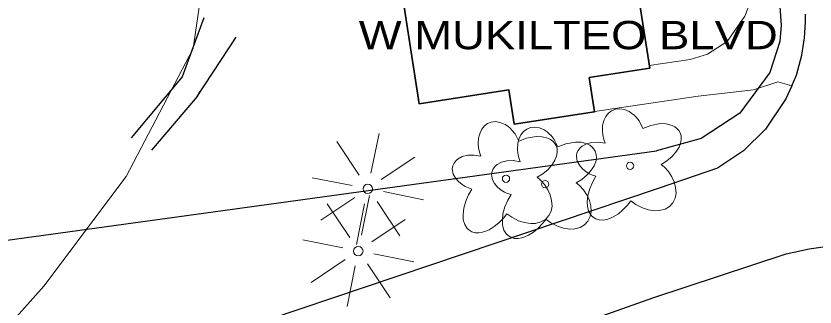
# Model space of a CAD drawing. Extents: x -861682 to -858969, y -1797841 to -1795153.
# Drawn here: x -859343 to -859173.6, y -1796365.6 to -1796304 of the extents above; entities that cross this region are included whole.
import ezdxf

# ---------------------------------------------------------------- set-up
doc = ezdxf.new("R2010")
doc.units = 0
doc.header["$LTSCALE"] = 2.4
for name, color, linetype, lineweight in [('10', 7, 'Continuous', 25), ('11', 7, 'Continuous', 13), ('12', 7, 'Continuous', 35), ('14', 7, 'Continuous', 25), ('17', 7, 'Continuous', 13), ('18', 7, 'Continuous', 13), ('42', 7, 'Continuous', 25), ('46', 7, 'Continuous', 13)]:
    doc.layers.add(name, color=color, linetype=linetype, lineweight=lineweight)

msp = doc.modelspace()

# ---------------------------------------------------------------- linework, layer by layer
at = {"layer": '10'}
for points in [[(-859178.581, -1796318.805), (-859177.592, -1796316.526), (-859176.417, -1796312.281), (-859175.841, -1796308.614), (-859175.653, -1796305.314), (-859175.676, -1796303.62)], [(-859178.581, -1796318.805), (-859179.784, -1796321.576), (-859184.102, -1796327.95), (-859188.824, -1796332.564), (-859194.317, -1796336.227)], [(-859194.317, -1796336.227), (-859199.045, -1796337.856), (-859206.902, -1796340.557), (-859310.306, -1796375.338)], [(-859179.756, -1796354.374), (-859174.867, -1796353.331), (-859165.467, -1796352.018), (-859159.969, -1796351.66), (-859156.664, -1796351.588), (-859155.562, -1796351.589), (-859151.156, -1796351.708), (-859147.857, -1796351.924), (-859141.289, -1796352.676), (-859135.862, -1796353.628)], [(-859313.301, -1796404.44), (-859308.712, -1796402.455), (-859282.34, -1796391.428), (-859240.21, -1796375.108), (-859208.017, -1796363.681), (-859179.756, -1796354.374)]]:
    msp.add_lwpolyline(points, dxfattribs=at)
at = {"layer": '11'}
for points in [[(-859213.77, -1796282.438), (-859199.161, -1796280.705), (-859189.027, -1796280.435), (-859186.317, -1796298.368), (-859188.538, -1796304.075), (-859192.284, -1796309.415), (-859196.439, -1796312.061), (-859200.087, -1796313.189), (-859208.753, -1796314.468)], [(-859220.349, -1796324.265), (-859198.422, -1796321.014), (-859186.678, -1796319.641), (-859181.524, -1796317.965), (-859178.581, -1796318.805)]]:
    msp.add_lwpolyline(points, dxfattribs=at)
at = {"layer": '12'}
msp.add_lwpolyline([(-859208.662, -1796315.05), (-859215.682, -1796270.238), (-859234.98, -1796273.261), (-859234.92, -1796273.647), (-859244.362, -1796275.115), (-859242.086, -1796289.756), (-859262.133, -1796292.872), (-859257.51, -1796322.614), (-859238.501, -1796319.659), (-859237.37, -1796326.931), (-859220.346, -1796324.283), (-859221.473, -1796317.043)], close=True, dxfattribs=at)
at = {"layer": '14'}
msp.add_line((-859304.601, -1796321.056), (-859314.241, -1796332.457), dxfattribs=at)
for points in [[(-859303.178, -1796304.397), (-859307.751, -1796316.893), (-859318.601, -1796329.807)], [(-859303.992, -1796320.022), (-859304.601, -1796321.056), (-859296.313, -1796308.51)]]:
    msp.add_lwpolyline(points, dxfattribs=at)
at = {"layer": '17'}
for p, q in [((-859267.756, -1796337.27), (-859266.03, -1796328.87)), ((-859270.216, -1796337.73), (-859275.006, -1796330.602)), ((-859265.556, -1796338.67), (-859258.46, -1796333.93)), ((-859271.716, -1796339.93), (-859280.178, -1796338.256)), ((-859271.176, -1796342.43), (-859278.402, -1796347.286)), ((-859269.766, -1796350.438), (-859268.04, -1796342.038)), ((-859265.116, -1796341.19), (-859256.636, -1796342.914)), ((-859272.226, -1796350.898), (-859277.016, -1796343.77)), ((-859270.796, -1796352.39), (-859269.116, -1796343.79)), ((-859266.456, -1796343.33), (-859261.656, -1796350.544)), ((-859267.566, -1796351.838), (-859260.47, -1796347.098)), ((-859273.726, -1796353.098), (-859282.188, -1796351.424)), ((-859267.126, -1796354.358), (-859258.646, -1796356.082)), ((-859273.186, -1796355.598), (-859280.412, -1796360.454)), ((-859272.806, -1796365.558), (-859271.126, -1796356.958)), ((-859268.466, -1796356.498), (-859263.666, -1796363.712))]:
    msp.add_line(p, q, dxfattribs=at)
for points in [[(-859212.649, -1796343.157), (-859211.607, -1796343.925), (-859210.201, -1796344.647), (-859208.953, -1796345.053), (-859207.581, -1796345.249), (-859206.563, -1796345.199), (-859205.419, -1796344.909), (-859204.487, -1796344.357), (-859203.747, -1796343.569), (-859203.279, -1796342.611), (-859203.069, -1796341.533), (-859203.173, -1796340.337), (-859203.463, -1796339.165), (-859203.949, -1796338.105), (-859204.671, -1796336.961), (-859205.537, -1796336.041), (-859206.219, -1796335.429), (-859205.037, -1796334.713), (-859203.891, -1796333.765), (-859202.971, -1796332.673), (-859202.449, -1796331.817), (-859202.117, -1796331.003), (-859201.971, -1796330.187), (-859202.011, -1796329.425), (-859202.227, -1796328.745), (-859202.485, -1796328.293), (-859202.905, -1796327.819), (-859203.365, -1796327.465), (-859203.931, -1796327.175), (-859205.167, -1796326.847), (-859206.409, -1796326.813), (-859208.455, -1796327.189), (-859210.115, -1796327.827), (-859210.905, -1796326.249), (-859211.559, -1796325.435), (-859211.971, -1796325.033), (-859212.435, -1796324.633), (-859213.037, -1796324.241), (-859214.041, -1796323.809), (-859215.055, -1796323.639), (-859215.943, -1796323.739), (-859216.743, -1796324.073), (-859217.409, -1796324.559), (-859217.969, -1796325.265), (-859218.319, -1796326.021), (-859218.477, -1796326.459), (-859218.645, -1796327.135), (-859218.697, -1796328.297), (-859218.625, -1796329.195), (-859218.413, -1796330.157), (-859218.129, -1796330.963), (-859219.571, -1796330.731), (-859220.929, -1796330.781), (-859222.087, -1796331.067), (-859222.975, -1796331.565), (-859223.415, -1796331.909), (-859223.849, -1796332.475), (-859224.087, -1796333.009), (-859224.211, -1796333.687), (-859224.009, -1796334.791), (-859223.553, -1796335.603), (-859222.929, -1796336.365), (-859222.151, -1796336.981), (-859221.453, -1796337.405), (-859220.789, -1796337.693), (-859220.061, -1796337.931), (-859220.745, -1796339.143), (-859221.367, -1796340.511), (-859221.763, -1796342.013), (-859221.897, -1796343.347), (-859221.887, -1796344.437), (-859221.553, -1796345.455), (-859221.031, -1796346.301), (-859220.473, -1796346.737), (-859220.087, -1796346.983), (-859219.353, -1796347.207), (-859218.559, -1796347.219), (-859217.789, -1796347.095), (-859217.129, -1796346.883), (-859216.385, -1796346.561), (-859215.309, -1796345.881), (-859214.347, -1796345.095), (-859213.391, -1796344.077), (-859212.645, -1796343.167)], [(-859238.946, -1796345.885), (-859237.904, -1796346.653), (-859236.498, -1796347.375), (-859235.25, -1796347.781), (-859233.878, -1796347.977), (-859232.86, -1796347.927), (-859231.716, -1796347.637), (-859230.784, -1796347.085), (-859230.044, -1796346.297), (-859229.576, -1796345.339), (-859229.366, -1796344.261), (-859229.47, -1796343.065), (-859229.76, -1796341.893), (-859230.246, -1796340.833), (-859230.968, -1796339.689), (-859231.834, -1796338.769), (-859232.516, -1796338.157), (-859231.334, -1796337.441), (-859230.188, -1796336.493), (-859229.268, -1796335.401), (-859228.746, -1796334.545), (-859228.414, -1796333.731), (-859228.268, -1796332.915), (-859228.308, -1796332.153), (-859228.524, -1796331.473), (-859228.782, -1796331.021), (-859229.202, -1796330.547), (-859229.662, -1796330.193), (-859230.228, -1796329.903), (-859231.464, -1796329.575), (-859232.706, -1796329.541), (-859234.752, -1796329.917), (-859236.412, -1796330.555), (-859237.202, -1796328.977), (-859237.856, -1796328.163), (-859238.268, -1796327.761), (-859238.732, -1796327.361), (-859239.334, -1796326.969), (-859240.338, -1796326.537), (-859241.352, -1796326.367), (-859242.24, -1796326.467), (-859243.04, -1796326.801), (-859243.706, -1796327.287), (-859244.266, -1796327.993), (-859244.616, -1796328.749), (-859244.774, -1796329.187), (-859244.942, -1796329.863), (-859244.994, -1796331.025), (-859244.922, -1796331.923), (-859244.71, -1796332.885), (-859244.426, -1796333.691), (-859245.868, -1796333.459), (-859247.226, -1796333.509), (-859248.384, -1796333.795), (-859249.272, -1796334.293), (-859249.712, -1796334.637), (-859250.146, -1796335.203), (-859250.384, -1796335.737), (-859250.508, -1796336.415), (-859250.306, -1796337.519), (-859249.85, -1796338.331), (-859249.226, -1796339.093), (-859248.448, -1796339.709), (-859247.75, -1796340.133), (-859247.086, -1796340.421), (-859246.358, -1796340.659), (-859247.042, -1796341.871), (-859247.664, -1796343.239), (-859248.06, -1796344.741), (-859248.194, -1796346.075), (-859248.184, -1796347.165), (-859247.85, -1796348.183), (-859247.328, -1796349.029), (-859246.77, -1796349.465), (-859246.384, -1796349.711), (-859245.65, -1796349.935), (-859244.856, -1796349.947), (-859244.086, -1796349.823), (-859243.426, -1796349.611), (-859242.682, -1796349.289), (-859241.606, -1796348.609), (-859240.644, -1796347.823), (-859239.688, -1796346.805), (-859238.942, -1796345.895)], [(-859230.65, -1796347.057), (-859229.608, -1796347.825), (-859228.202, -1796348.547), (-859226.954, -1796348.953), (-859225.582, -1796349.149), (-859224.564, -1796349.099), (-859223.42, -1796348.809), (-859222.488, -1796348.257), (-859221.748, -1796347.469), (-859221.28, -1796346.511), (-859221.07, -1796345.433), (-859221.174, -1796344.237), (-859221.464, -1796343.065), (-859221.95, -1796342.005), (-859222.672, -1796340.861), (-859223.538, -1796339.941), (-859224.22, -1796339.329), (-859223.038, -1796338.613), (-859221.892, -1796337.665), (-859220.972, -1796336.573), (-859220.45, -1796335.717), (-859220.118, -1796334.903), (-859219.972, -1796334.087), (-859220.012, -1796333.325), (-859220.228, -1796332.645), (-859220.486, -1796332.193), (-859220.906, -1796331.719), (-859221.366, -1796331.365), (-859221.932, -1796331.075), (-859223.168, -1796330.747), (-859224.41, -1796330.713), (-859226.456, -1796331.089), (-859228.116, -1796331.727), (-859228.906, -1796330.149), (-859229.56, -1796329.335), (-859229.972, -1796328.933), (-859230.436, -1796328.533), (-859231.038, -1796328.141), (-859232.042, -1796327.709), (-859233.056, -1796327.539), (-859233.944, -1796327.639), (-859234.744, -1796327.973), (-859235.41, -1796328.459), (-859235.97, -1796329.165), (-859236.32, -1796329.921), (-859236.478, -1796330.359), (-859236.646, -1796331.035), (-859236.698, -1796332.197), (-859236.626, -1796333.095), (-859236.414, -1796334.057), (-859236.13, -1796334.863), (-859237.572, -1796334.631), (-859238.93, -1796334.681), (-859240.088, -1796334.967), (-859240.976, -1796335.465), (-859241.416, -1796335.809), (-859241.85, -1796336.375), (-859242.088, -1796336.909), (-859242.212, -1796337.587), (-859242.01, -1796338.691), (-859241.554, -1796339.503), (-859240.93, -1796340.265), (-859240.152, -1796340.881), (-859239.454, -1796341.305), (-859238.79, -1796341.593), (-859238.062, -1796341.831), (-859238.746, -1796343.043), (-859239.368, -1796344.411), (-859239.764, -1796345.913), (-859239.898, -1796347.247), (-859239.888, -1796348.337), (-859239.554, -1796349.355), (-859239.032, -1796350.201), (-859238.474, -1796350.637), (-859238.088, -1796350.883), (-859237.354, -1796351.107), (-859236.56, -1796351.119), (-859235.79, -1796350.995), (-859235.13, -1796350.783), (-859234.386, -1796350.461), (-859233.31, -1796349.781), (-859232.348, -1796348.995), (-859231.392, -1796347.977), (-859230.646, -1796347.067)]]:
    msp.add_lwpolyline(points, dxfattribs=at)
for centre, radius in [((-859212.829, -1796335.745), 0.773), ((-859239.126, -1796338.473), 0.773), ((-859230.83, -1796339.645), 0.773), ((-859268.416, -1796340.63), 1), ((-859270.426, -1796353.798), 1)]:
    msp.add_circle(centre, radius, dxfattribs=at)
at = {"layer": '18'}
msp.add_lwpolyline([(-859347.215, -1796129.795), (-859321.586, -1796150.045), (-859299.228, -1796169.09), (-859292.462, -1796192.945), (-859295.557, -1796234.584), (-859300.563, -1796261.567), (-859301.495, -1796283.615), (-859305.463, -1796310.868), (-859319.613, -1796338.001), (-859337.091, -1796361.222), (-859367.474, -1796395.166), (-859401.932, -1796399.926), (-859462.09, -1796406.183), (-859502.465, -1796413.666), (-859545.868, -1796417.533)], dxfattribs=at)
at = {"layer": '42'}
for p, q in [((-859185.103, -1796248.411), (-859180.813, -1796305.925)), ((-859429.066, -1796363.089), (-859207.259, -1796332.597))]:
    msp.add_line(p, q, dxfattribs=at)
msp.add_lwpolyline([(-859180.813, -1796305.925), (-859181.114, -1796309.394), (-859183.174, -1796315.962), (-859189.573, -1796324.57), (-859197.742, -1796329.966), (-859207.259, -1796332.597)], dxfattribs=at)

# ---------------------------------------------------------------- texts
at = {"layer": '46', "width": 1.2}
msp.add_text('W MUKILTEO BLVD', height=6, dxfattribs=at).set_placement((-859270.336, -1796311.052))

doc.saveas('drawing.dxf')
